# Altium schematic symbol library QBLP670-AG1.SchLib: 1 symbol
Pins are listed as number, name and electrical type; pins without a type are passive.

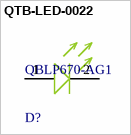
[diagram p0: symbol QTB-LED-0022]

## QTB-LED-0022
designator D?, comment QBLP670-AG1
LED YELLOW/GREEN CLEAR 2PLCC SMD; Manufacturer: QT Brightek (QTB); Luminous Intensity: 85mcd; Test Current: 20mA; Lens Color: Colorless; Lens Style: Oval with Flat Top; Forward Voltage: 2.0V; Wavelength - Dominant: 569nm; Viewing Angle: 120°
footprint QBLP670-AG1
pins: 1 ANODE (+), 2 CATHODE (-)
